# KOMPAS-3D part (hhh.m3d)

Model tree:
1. Эскиз:1
2. Операция выдавливания:1
     Расстояние 1 = 65; Расстояние 2 = 20
3. Эскиз:2
4. Вырезать элемент выдавливания:1
     Расстояние 1 = 20
5. Эскиз:3
6. Вырезать элемент выдавливания:2
     Расстояние 1 = 20
7. Эскиз:4
8. Операция выдавливания:2
     Расстояние 1 = 60; Угол 1 = 6; Расстояние 2 = 60; Угол 2 = 3
9. Эскиз:5
10. Вырезать элемент выдавливания:3
     Расстояние 1 = 40
